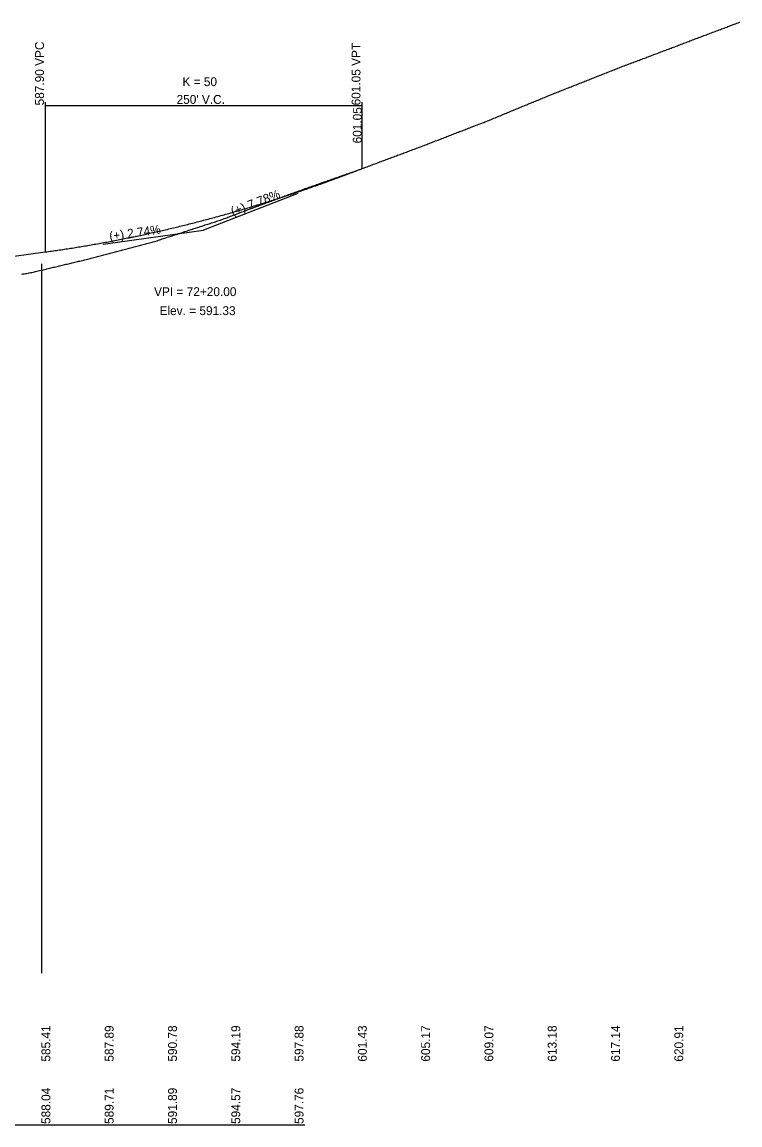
# Model space of a CAD drawing. Extents: x 1622419 to 1631737, y 887848 to 892020.
# Drawn here: x 1623574 to 1624141, y 890770 to 891641 of the extents above; entities that cross this region are included whole.
import ezdxf

# ---------------------------------------------------------------- set-up
doc = ezdxf.new("R2010")
doc.units = 0
for name, color, linetype in [('RD_DDB_GradeTX', 7, 'Continuous'), ('RD_DDB_Profile_EX', 7, 'Continuous'), ('RD_DDB_Profile_Lbl', 7, 'Continuous'), ('RD_DDB_Profile_PR', 7, 'Continuous'), ('RD_DDB_StripGrade', 7, 'Continuous'), ('RD_DDB_VCLbl', 7, 'Continuous'), ('RD_GPK_Profile_Cell', 7, 'Continuous'), ('RD_PD_Bridge', 7, 'Continuous')]:
    doc.layers.add(name, color=color, linetype=linetype)

msp = doc.modelspace()

# ---------------------------------------------------------------- linework, layer by layer
at = {"layer": 'RD_DDB_GradeTX'}
for p in [(1623791.58, 891505.66), (1623637.76, 891465.79)]:
    msp.add_line(p, (1623717.02, 891476.67), dxfattribs=at)
at = {"layer": 'RD_DDB_Profile_EX'}
for points in [[(1624087.38, 891620.9), (1624088.38, 891621.28), (1624089.38, 891621.66), (1624090.38, 891622.03), (1624091.38, 891622.42), (1624092.38, 891622.81), (1624093.38, 891623.19), (1624094.38, 891623.57), (1624095.38, 891623.95), (1624096.38, 891624.33), (1624097.38, 891624.71), (1624098.38, 891625.09), (1624099.38, 891625.46), (1624100.38, 891625.84), (1624101.38, 891626.22), (1624102.38, 891626.6), (1624103.38, 891626.98), (1624104.38, 891627.36), (1624105.38, 891627.74), (1624106.38, 891628.12), (1624107.38, 891628.5), (1624108.38, 891628.88), (1624109.38, 891629.25), (1624110.38, 891629.63), (1624111.38, 891630.01), (1624112.38, 891630.38), (1624113.38, 891630.76), (1624114.38, 891631.14), (1624115.38, 891631.52), (1624116.38, 891631.89), (1624117.38, 891632.27), (1624118.38, 891632.65), (1624119.38, 891633.02), (1624120.38, 891633.4), (1624121.38, 891633.78), (1624122.38, 891634.15), (1624123.38, 891634.53), (1624124.38, 891634.91), (1624125.38, 891635.29), (1624126.38, 891635.66), (1624127.38, 891636.04), (1624128.38, 891636.42), (1624129.38, 891636.79), (1624130.38, 891637.17), (1624131.38, 891637.55), (1624132.38, 891637.92), (1624133.38, 891638.3), (1624134.38, 891638.68), (1624135.38, 891639.06), (1624136.38, 891639.43), (1624137.38, 891639.81), (1624138.38, 891640.19), (1624139.38, 891640.56), (1624140.38, 891640.94), (1624140.85, 891641.12)], [(1623987.38, 891582.01), (1623988.38, 891582.42), (1623989.38, 891582.83), (1623990.38, 891583.25), (1623991.38, 891583.66), (1623992.38, 891584.06), (1623993.38, 891584.45), (1623994.38, 891584.85), (1623995.38, 891585.25), (1623996.38, 891585.64), (1623997.38, 891586.04), (1623998.38, 891586.43), (1623999.38, 891586.83), (1624000.38, 891587.23), (1624001.38, 891587.62), (1624002.38, 891588.02), (1624003.38, 891588.42), (1624004.38, 891588.81), (1624005.38, 891589.21), (1624006.38, 891589.6), (1624007.38, 891590), (1624008.38, 891590.4), (1624009.38, 891590.79), (1624010.38, 891591.19), (1624011.38, 891591.59), (1624012.38, 891591.98), (1624013.38, 891592.38), (1624014.38, 891592.77), (1624015.38, 891593.17), (1624016.38, 891593.57), (1624017.38, 891593.96), (1624018.38, 891594.36), (1624019.38, 891594.75), (1624020.38, 891595.15), (1624021.38, 891595.55), (1624022.38, 891595.94), (1624023.38, 891596.34), (1624024.38, 891596.74), (1624025.38, 891597.13), (1624026.38, 891597.53), (1624027.38, 891597.92), (1624028.38, 891598.32), (1624029.38, 891598.72), (1624030.38, 891599.11), (1624031.38, 891599.51), (1624032.38, 891599.91), (1624033.38, 891600.3), (1624034.38, 891600.7), (1624035.38, 891601.09), (1624036.38, 891601.49), (1624037.38, 891601.89), (1624038.38, 891602.28), (1624039.38, 891602.68), (1624040.38, 891603.08), (1624041.38, 891603.49), (1624042.38, 891603.89), (1624043.38, 891604.29), (1624044.38, 891604.7), (1624045.38, 891605.08), (1624046.38, 891605.45), (1624047.38, 891605.83), (1624048.38, 891606.21), (1624049.38, 891606.59), (1624050.38, 891606.96), (1624051.38, 891607.34), (1624052.38, 891607.72), (1624053.38, 891608.09), (1624054.38, 891608.47), (1624055.38, 891608.85), (1624056.38, 891609.22), (1624057.38, 891609.6), (1624058.38, 891609.98), (1624059.38, 891610.35), (1624060.38, 891610.73), (1624061.38, 891611.11), (1624062.38, 891611.48), (1624063.38, 891611.86), (1624064.38, 891612.24), (1624065.38, 891612.61), (1624066.38, 891612.99), (1624067.38, 891613.37), (1624068.38, 891613.74), (1624069.38, 891614.12), (1624070.38, 891614.5), (1624071.38, 891614.88), (1624072.38, 891615.25), (1624073.38, 891615.63), (1624074.38, 891616.01), (1624075.38, 891616.38), (1624076.38, 891616.76), (1624077.38, 891617.14), (1624078.38, 891617.51), (1624079.38, 891617.89), (1624080.38, 891618.27), (1624081.38, 891618.64), (1624082.38, 891619.02), (1624083.38, 891619.4), (1624084.38, 891619.77), (1624085.38, 891620.15), (1624086.38, 891620.53), (1624087.38, 891620.9)], [(1623887.38, 891542.19), (1623888.38, 891542.56), (1623889.38, 891542.93), (1623890.38, 891543.3), (1623891.38, 891543.68), (1623892.38, 891544.07), (1623893.38, 891544.45), (1623894.38, 891544.84), (1623895.38, 891545.23), (1623896.38, 891545.62), (1623897.38, 891546.01), (1623898.38, 891546.4), (1623899.38, 891546.79), (1623900.38, 891547.18), (1623901.38, 891547.57), (1623902.38, 891547.96), (1623903.38, 891548.35), (1623904.38, 891548.73), (1623905.38, 891549.12), (1623906.38, 891549.51), (1623907.38, 891549.9), (1623908.38, 891550.29), (1623909.38, 891550.68), (1623910.38, 891551.06), (1623911.38, 891551.45), (1623912.38, 891551.84), (1623913.38, 891552.23), (1623914.38, 891552.62), (1623915.38, 891553), (1623916.38, 891553.39), (1623917.38, 891553.78), (1623918.38, 891554.16), (1623919.38, 891554.55), (1623920.38, 891554.94), (1623921.38, 891555.33), (1623922.38, 891555.71), (1623923.38, 891556.1), (1623924.38, 891556.49), (1623925.38, 891556.87), (1623926.38, 891557.26), (1623927.38, 891557.65), (1623928.38, 891558.03), (1623929.38, 891558.42), (1623930.38, 891558.8), (1623931.38, 891559.19), (1623932.38, 891559.58), (1623933.38, 891559.96), (1623934.38, 891560.35), (1623935.38, 891560.73), (1623936.38, 891561.12), (1623937.38, 891561.5), (1623938.38, 891561.89), (1623939.38, 891562.27), (1623940.38, 891562.66), (1623941.38, 891563.04), (1623942.38, 891563.43), (1623943.38, 891563.85), (1623944.38, 891564.26), (1623945.38, 891564.68), (1623946.38, 891565.09), (1623947.38, 891565.51), (1623948.38, 891565.92), (1623949.38, 891566.34), (1623950.38, 891566.75), (1623951.38, 891567.16), (1623952.38, 891567.58), (1623953.38, 891567.99), (1623954.38, 891568.41), (1623955.38, 891568.82), (1623956.38, 891569.23), (1623957.38, 891569.65), (1623958.38, 891570.06), (1623959.38, 891570.47), (1623960.38, 891570.89), (1623961.38, 891571.3), (1623962.38, 891571.71), (1623963.38, 891572.13), (1623964.38, 891572.54), (1623965.38, 891572.95), (1623966.38, 891573.37), (1623967.38, 891573.78), (1623968.38, 891574.19), (1623969.38, 891574.6), (1623970.38, 891575.01), (1623971.38, 891575.43), (1623972.38, 891575.84), (1623973.38, 891576.25), (1623974.38, 891576.66), (1623975.38, 891577.07), (1623976.38, 891577.49), (1623977.38, 891577.9), (1623978.38, 891578.31), (1623979.38, 891578.72), (1623980.38, 891579.13), (1623981.38, 891579.54), (1623982.38, 891579.95), (1623983.38, 891580.37), (1623984.38, 891580.78), (1623985.38, 891581.19), (1623986.38, 891581.6), (1623987.38, 891582.01)], [(1623787.38, 891505.94), (1623788.38, 891506.3), (1623789.38, 891506.66), (1623790.38, 891507.02), (1623791.38, 891507.38), (1623792.38, 891507.74), (1623793.38, 891508.1), (1623794.38, 891508.46), (1623795.38, 891508.81), (1623796.38, 891509.17), (1623797.38, 891509.53), (1623798.38, 891509.89), (1623799.38, 891510.24), (1623800.38, 891510.6), (1623801.38, 891510.96), (1623802.38, 891511.31), (1623803.38, 891511.67), (1623804.38, 891512.02), (1623805.38, 891512.37), (1623806.38, 891512.73), (1623807.38, 891513.08), (1623808.38, 891513.43), (1623809.38, 891513.78), (1623810.38, 891514.13), (1623811.38, 891514.48), (1623812.38, 891514.83), (1623813.38, 891515.18), (1623814.38, 891515.53), (1623815.38, 891515.88), (1623816.38, 891516.23), (1623817.38, 891516.58), (1623818.38, 891516.93), (1623819.38, 891517.28), (1623820.38, 891517.63), (1623821.38, 891517.98), (1623822.38, 891518.33), (1623823.38, 891518.68), (1623824.38, 891519.03), (1623825.38, 891519.38), (1623826.38, 891519.73), (1623827.38, 891520.08), (1623828.38, 891520.43), (1623829.38, 891520.77), (1623830.38, 891521.12), (1623831.38, 891521.47), (1623832.38, 891521.82), (1623833.38, 891522.17), (1623834.38, 891522.52), (1623835.38, 891522.87), (1623836.38, 891523.21), (1623837.38, 891523.56), (1623838.38, 891523.91), (1623839.38, 891524.28), (1623840.38, 891524.65), (1623841.38, 891525.03), (1623842.38, 891525.4), (1623843.38, 891525.78), (1623844.38, 891526.15), (1623845.38, 891526.53), (1623846.38, 891526.9), (1623847.38, 891527.28), (1623848.38, 891527.65), (1623849.38, 891528.03), (1623850.38, 891528.4), (1623851.38, 891528.78), (1623852.38, 891529.15), (1623853.38, 891529.53), (1623854.38, 891529.9), (1623855.38, 891530.27), (1623856.38, 891530.65), (1623857.38, 891531.02), (1623858.38, 891531.4), (1623859.38, 891531.77), (1623860.38, 891532.14), (1623861.38, 891532.52), (1623862.38, 891532.89), (1623863.38, 891533.26), (1623864.38, 891533.64), (1623865.38, 891534.01), (1623866.38, 891534.38), (1623867.38, 891534.75), (1623868.38, 891535.13), (1623869.38, 891535.5), (1623870.38, 891535.87), (1623871.38, 891536.24), (1623872.38, 891536.62), (1623873.38, 891536.99), (1623874.38, 891537.36), (1623875.38, 891537.73), (1623876.38, 891538.1), (1623877.38, 891538.48), (1623878.38, 891538.85), (1623879.38, 891539.22), (1623880.38, 891539.59), (1623881.38, 891539.96), (1623882.38, 891540.33), (1623883.38, 891540.7), (1623884.38, 891541.08), (1623885.38, 891541.45), (1623886.38, 891541.82), (1623887.38, 891542.19)], [(1623687.38, 891470.76), (1623688.38, 891471.09), (1623689.38, 891471.42), (1623690.38, 891471.75), (1623691.38, 891472.07), (1623692.38, 891472.4), (1623693.38, 891472.73), (1623694.38, 891473.06), (1623695.38, 891473.38), (1623696.38, 891473.71), (1623697.38, 891474.04), (1623698.38, 891474.36), (1623699.38, 891474.69), (1623700.38, 891475.02), (1623701.38, 891475.34), (1623702.38, 891475.67), (1623703.38, 891475.99), (1623704.38, 891476.32), (1623705.38, 891476.64), (1623706.38, 891476.97), (1623707.38, 891477.29), (1623708.38, 891477.62), (1623709.38, 891477.94), (1623710.38, 891478.27), (1623711.38, 891478.59), (1623712.38, 891478.91), (1623713.38, 891479.24), (1623714.38, 891479.56), (1623715.38, 891479.88), (1623716.38, 891480.21), (1623717.38, 891480.53), (1623718.38, 891480.85), (1623719.38, 891481.18), (1623720.38, 891481.5), (1623721.38, 891481.82), (1623722.38, 891482.14), (1623723.38, 891482.46), (1623724.38, 891482.79), (1623725.38, 891483.11), (1623726.38, 891483.43), (1623727.38, 891483.75), (1623728.38, 891484.07), (1623729.38, 891484.39), (1623730.38, 891484.72), (1623731.38, 891485.09), (1623732.38, 891485.47), (1623733.38, 891485.85), (1623734.38, 891486.23), (1623735.38, 891486.61), (1623736.38, 891486.98), (1623737.38, 891487.36), (1623738.38, 891487.74), (1623739.38, 891488.12), (1623740.38, 891488.49), (1623741.38, 891488.87), (1623742.38, 891489.24), (1623743.38, 891489.62), (1623744.38, 891490), (1623745.38, 891490.37), (1623746.38, 891490.75), (1623747.38, 891491.12), (1623748.38, 891491.5), (1623749.38, 891491.87), (1623750.38, 891492.25), (1623751.38, 891492.62), (1623752.38, 891493), (1623753.38, 891493.37), (1623754.38, 891493.75), (1623755.38, 891494.12), (1623756.38, 891494.49), (1623757.38, 891494.87), (1623758.38, 891495.24), (1623759.38, 891495.61), (1623760.38, 891495.99), (1623761.38, 891496.36), (1623762.38, 891496.73), (1623763.38, 891497.1), (1623764.38, 891497.48), (1623765.38, 891497.85), (1623766.38, 891498.22), (1623767.38, 891498.59), (1623768.38, 891498.96), (1623769.38, 891499.33), (1623770.38, 891499.7), (1623771.38, 891500.08), (1623772.38, 891500.45), (1623773.38, 891500.82), (1623774.38, 891501.19), (1623775.38, 891501.56), (1623776.38, 891501.93), (1623777.38, 891502.3), (1623778.38, 891502.67), (1623779.38, 891503.03), (1623780.38, 891503.4), (1623781.38, 891503.77), (1623782.38, 891504.14), (1623783.38, 891504.5), (1623784.38, 891504.86), (1623785.38, 891505.22), (1623786.38, 891505.58), (1623787.38, 891505.94)], [(1623587.38, 891444.81), (1623588.38, 891445.05), (1623589.38, 891445.28), (1623590.38, 891445.52), (1623591.38, 891445.75), (1623592.38, 891445.99), (1623593.38, 891446.23), (1623594.38, 891446.46), (1623595.38, 891446.7), (1623596.38, 891446.93), (1623597.38, 891447.17), (1623598.38, 891447.41), (1623599.38, 891447.64), (1623600.38, 891447.88), (1623601.38, 891448.11), (1623602.38, 891448.35), (1623603.38, 891448.59), (1623604.38, 891448.82), (1623605.38, 891449.06), (1623606.38, 891449.29), (1623607.38, 891449.53), (1623608.38, 891449.77), (1623609.38, 891450), (1623610.38, 891450.24), (1623611.38, 891450.48), (1623612.38, 891450.71), (1623613.38, 891450.95), (1623614.38, 891451.19), (1623615.38, 891451.42), (1623616.38, 891451.66), (1623617.38, 891451.9), (1623618.38, 891452.14), (1623619.38, 891452.37), (1623620.38, 891452.61), (1623621.38, 891452.85), (1623622.38, 891453.08), (1623623.38, 891453.32), (1623624.38, 891453.56), (1623625.38, 891453.8), (1623626.38, 891454.03), (1623627.38, 891454.27), (1623628.38, 891454.51), (1623629.38, 891454.79), (1623630.38, 891455.06), (1623631.38, 891455.32), (1623632.38, 891455.59), (1623633.38, 891455.85), (1623634.38, 891456.12), (1623635.38, 891456.39), (1623636.38, 891456.65), (1623637.38, 891456.92), (1623638.38, 891457.19), (1623639.38, 891457.45), (1623640.38, 891457.72), (1623641.38, 891457.99), (1623642.38, 891458.25), (1623643.38, 891458.52), (1623644.38, 891458.79), (1623645.38, 891459.05), (1623646.38, 891459.32), (1623647.38, 891459.58), (1623648.38, 891459.85), (1623649.38, 891460.12), (1623650.38, 891460.38), (1623651.38, 891460.65), (1623652.38, 891460.92), (1623653.38, 891461.18), (1623654.38, 891461.45), (1623655.38, 891461.71), (1623656.38, 891461.98), (1623657.38, 891462.25), (1623658.38, 891462.51), (1623659.38, 891462.78), (1623660.38, 891463.05), (1623661.38, 891463.31), (1623662.38, 891463.58), (1623663.38, 891463.84), (1623664.38, 891464.11), (1623665.38, 891464.38), (1623666.38, 891464.64), (1623667.38, 891464.91), (1623668.38, 891465.17), (1623669.38, 891465.44), (1623670.38, 891465.71), (1623671.38, 891465.97), (1623672.38, 891466.24), (1623673.38, 891466.5), (1623674.38, 891466.77), (1623675.38, 891467.04), (1623676.38, 891467.3), (1623677.38, 891467.57), (1623678.38, 891467.83), (1623679.38, 891468.12), (1623680.38, 891468.45), (1623681.38, 891468.79), (1623682.38, 891469.12), (1623683.38, 891469.45), (1623684.38, 891469.77), (1623685.38, 891470.1), (1623686.38, 891470.43), (1623687.38, 891470.76)], [(1623573.38, 891441.98), (1623574.38, 891442.14), (1623575.38, 891442.3), (1623576.38, 891442.45), (1623577.38, 891442.63), (1623578.38, 891442.83), (1623579.38, 891443.03), (1623580.38, 891443.23), (1623581.38, 891443.42), (1623582.38, 891443.64), (1623583.38, 891443.87), (1623584.38, 891444.11), (1623585.38, 891444.34), (1623586.38, 891444.58), (1623587.38, 891444.81)]]:
    msp.add_lwpolyline(points, dxfattribs=at)
at = {"layer": 'RD_DDB_Profile_PR'}
msp.add_line((1623482.02, 891444.41), (1623592.02, 891459.51), dxfattribs=at)
msp.add_spline([(1623592.02, 891459.51), (1623597.02, 891460.21), (1623602.02, 891460.93), (1623607.02, 891461.68), (1623612.02, 891462.46), (1623617.02, 891463.26), (1623622.02, 891464.08), (1623627.02, 891464.93), (1623632.02, 891465.81), (1623637.02, 891466.71), (1623642.02, 891467.63), (1623647.02, 891468.58), (1623652.02, 891469.56), (1623657.02, 891470.56), (1623662.02, 891471.58), (1623667.02, 891472.63), (1623672.02, 891473.71), (1623677.02, 891474.81), (1623682.02, 891475.94), (1623687.02, 891477.09), (1623692.02, 891478.27), (1623697.02, 891479.47), (1623702.02, 891480.7), (1623707.02, 891481.95), (1623712.02, 891483.23), (1623717.02, 891484.53), (1623722.02, 891485.86), (1623727.02, 891487.21), (1623732.02, 891488.59), (1623737.02, 891489.99), (1623742.02, 891491.42), (1623747.02, 891492.87), (1623752.02, 891494.35), (1623757.02, 891495.86), (1623762.02, 891497.39), (1623767.02, 891498.94), (1623772.02, 891500.52), (1623777.02, 891502.12), (1623782.02, 891503.75), (1623787.02, 891505.41), (1623792.02, 891507.09), (1623797.02, 891508.79), (1623802.02, 891510.52), (1623807.02, 891512.28), (1623812.02, 891514.06), (1623817.02, 891515.87), (1623822.02, 891517.7), (1623827.02, 891519.55), (1623832.02, 891521.43), (1623837.02, 891523.34), (1623842.02, 891525.27)], degree=3, dxfattribs=at)
at = {"layer": 'RD_DDB_VCLbl'}
for p, q in [((1623592.02, 891577.77), (1623592.02, 891459.51)), ((1623592.02, 891575.27), (1623842.02, 891575.27)), ((1623842.02, 891577.77), (1623842.02, 891525.27))]:
    msp.add_line(p, q, dxfattribs=at)
at = {"layer": 'RD_GPK_Profile_Cell'}
msp.add_line((1622497.02, 890770.02), (1623797.02, 890770.02), dxfattribs=at)
at = {"layer": 'RD_PD_Bridge'}
msp.add_line((1623589.32, 890890.02), (1623589.32, 891450.27), dxfattribs=at)

# ---------------------------------------------------------------- texts
at = {"layer": 'RD_DDB_GradeTX'}
for s, rotation, p in [('(+) 7.78%', 21.24822, (1623740.22, 891487.83)), ('(+) 2.74%', 7.81488, (1623643.11, 891468.54))]:
    msp.add_text(s, height=7, rotation=rotation, dxfattribs=at).set_placement(p)
at = {"layer": 'RD_DDB_Profile_Lbl'}
msp.add_text('601.05', height=7, rotation=90, dxfattribs=at).set_placement((1623842.02, 891545.27))
for s, p in [('VPI = 72+20.00', (1623677.99, 891424.67)), ('Elev. = 591.33', (1623682.29, 891409.67))]:
    msp.add_text(s, height=7, dxfattribs=at).set_placement(p)
at = {"layer": 'RD_DDB_StripGrade'}
for s, p in [('587.90 VPC', (1623591.02, 891575.27)), ('601.05 VPT', (1623841.02, 891575.27)), ('585.41', (1623596.02, 890820.02)), ('587.89', (1623646.02, 890820.02)), ('590.78', (1623696.02, 890820.02)), ('594.19', (1623746.02, 890820.02)), ('597.88', (1623796.02, 890820.02)), ('601.43', (1623846.02, 890820.02)), ('605.17', (1623896.02, 890820.02)), ('609.07', (1623946.02, 890820.02)), ('613.18', (1623996.02, 890820.02)), ('617.14', (1624046.02, 890820.02)), ('620.91', (1624096.02, 890820.02)), ('588.04', (1623596.02, 890770.77)), ('589.71', (1623646.02, 890770.77)), ('591.89', (1623696.02, 890770.77)), ('594.57', (1623746.02, 890770.77)), ('597.76', (1623796.02, 890770.77))]:
    msp.add_text(s, height=7, rotation=90, dxfattribs=at).set_placement(p)
at = {"layer": 'RD_DDB_VCLbl'}
for s, p in [('K = 50', (1623700.4, 891590.52)), ("250' V.C.", (1623695.76, 891576.52))]:
    msp.add_text(s, height=7, dxfattribs=at).set_placement(p)

doc.saveas('drawing.dxf')
